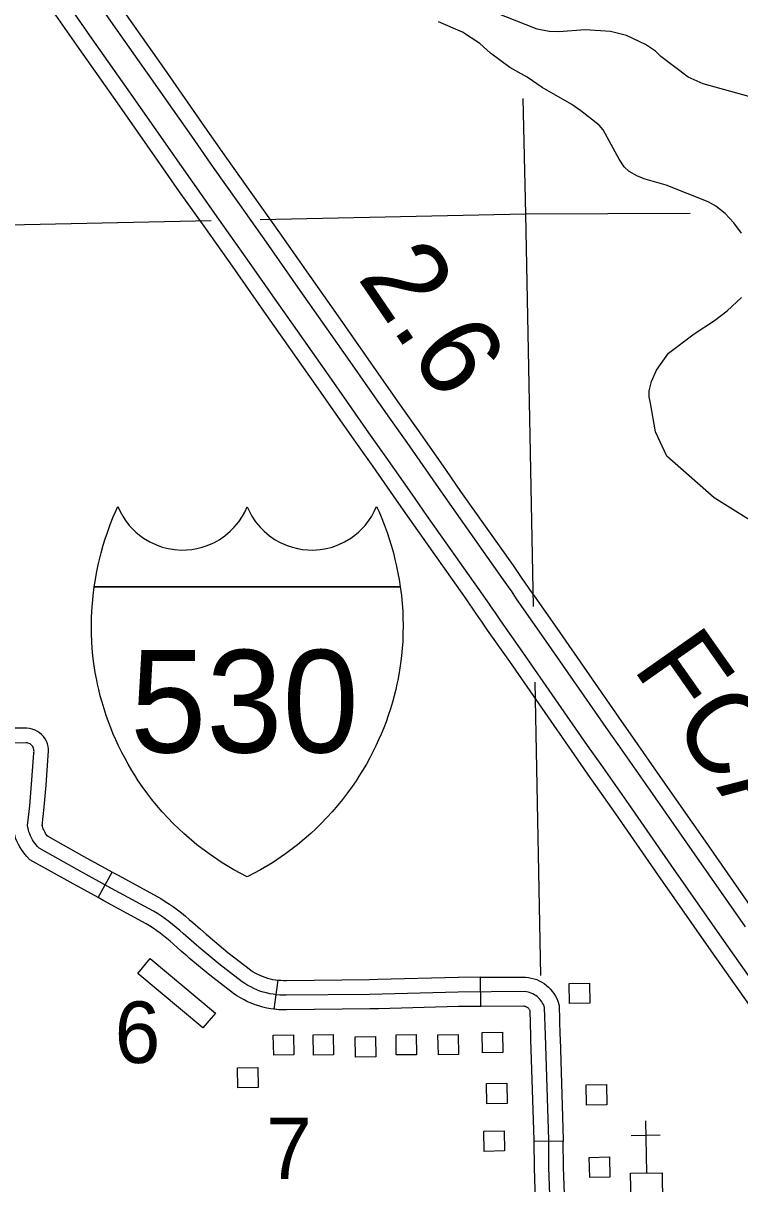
# Model space of a CAD drawing. Extents: x -19 to 366, y -4 to 359.
# Drawn here: x 157.737 to 158.436, y 175.04 to 176.172 of the extents above; entities that cross this region are included whole.
import ezdxf

# ---------------------------------------------------------------- set-up
doc = ezdxf.new("R2010")
doc.units = 0
for name, color, linetype in [('Level 19', 7, 'Continuous'), ('Level 23', 7, 'Continuous'), ('Level 26', 7, 'Continuous'), ('Level 31', 7, 'Continuous'), ('Level 35', 7, 'Continuous'), ('Level 47', 7, 'Continuous'), ('Level 48', 7, 'Continuous'), ('Level 5', 7, 'Continuous'), ('Level 56', 7, 'Continuous'), ('Level 57', 7, 'Continuous'), ('Level 60', 7, 'Continuous')]:
    doc.layers.add(name, color=color, linetype=linetype)

msp = doc.modelspace()

# ---------------------------------------------------------------- linework, layer by layer
at = {"layer": 'Level 19'}
for points in [[(157.777, 176.2397), (157.8247, 176.171), (157.8621, 176.1181), (157.9013, 176.0619), (157.9227, 176.0315), (157.9483, 175.9954), (157.9743, 175.9586), (158.0049, 175.9148), (158.0313, 175.8774), (158.0559, 175.8422), (158.0733, 175.8175), (158.0946, 175.787), (158.1116, 175.7632), (158.1369, 175.7268), (158.1512, 175.7062), (158.2024, 175.6339), (158.212, 175.6201), (158.2132, 175.6185), (158.2184, 175.6107), (158.2235, 175.6033), (158.245, 175.5728), (158.3081, 175.4819), (158.3213, 175.4632), (158.3486, 175.4241), (158.3897, 175.3651), (158.4416, 175.2906)], [(158.4685, 175.21), (158.4215, 175.2764), (158.3695, 175.351), (158.3284, 175.41), (158.3012, 175.4491), (158.2879, 175.4677), (158.2248, 175.5587), (158.2033, 175.5892), (158.198, 175.5969), (158.1933, 175.604), (158.1922, 175.6054), (158.1822, 175.6198), (158.1311, 175.6921), (158.1167, 175.7128), (158.0915, 175.749), (158.0745, 175.7728), (158.0531, 175.8034), (158.0358, 175.8281), (158.0111, 175.8633), (157.9848, 175.9007), (157.9541, 175.9444), (157.9282, 175.9812), (157.9026, 176.0172), (157.8811, 176.0478), (157.842, 176.1039), (157.8046, 176.1569), (157.7569, 176.2256)], [(157.7437, 176.2163), (157.7914, 176.1477), (157.8288, 176.0947), (157.8679, 176.0386), (157.8894, 176.0079), (157.9151, 175.9719), (157.941, 175.9352), (157.9716, 175.8914), (157.9979, 175.854), (158.0226, 175.8188), (158.0399, 175.7941), (158.0613, 175.7635), (158.0783, 175.7397), (158.1035, 175.7036), (158.1179, 175.6829), (158.169, 175.6106), (158.1793, 175.5958), (158.1803, 175.5945), (158.1847, 175.5879), (158.1901, 175.58), (158.2116, 175.5495), (158.2747, 175.4585), (158.288, 175.4398), (158.3152, 175.4008), (158.3563, 175.3418), (158.4083, 175.2672), (158.4553, 175.2007)], [(158.4548, 175.2999), (158.4029, 175.3743), (158.3618, 175.4333), (158.3345, 175.4725), (158.3212, 175.4911), (158.2582, 175.582), (158.2367, 175.6125), (158.2317, 175.6197), (158.2262, 175.628), (158.2249, 175.6297), (158.2156, 175.6432), (158.1644, 175.7155), (158.1501, 175.736), (158.1247, 175.7725), (158.1077, 175.7963), (158.0865, 175.8267), (158.0691, 175.8514), (158.0444, 175.8867), (158.0181, 175.9241), (157.9875, 175.9678), (157.9614, 176.0047), (157.9358, 176.0407), (157.9145, 176.0711), (157.8753, 176.1273), (157.8379, 176.1803)]]:
    msp.add_lwpolyline(points, dxfattribs=at)
at = {"layer": 'Level 23'}
for points in [[(157.8065, 175.6223), (157.8076, 175.6294), (157.8087, 175.6357), (157.8104, 175.6439), (157.8116, 175.6492), (157.8132, 175.6555), (157.8153, 175.6629), (157.8172, 175.6691), (157.8193, 175.6754), (157.8222, 175.6833), (157.8251, 175.6906), (157.8275, 175.6963), (157.8296, 175.7008), (157.8317, 175.696), (157.8343, 175.6914), (157.8371, 175.6871), (157.8407, 175.6824), (157.8436, 175.6792), (157.8471, 175.6758), (157.8507, 175.6728), (157.8546, 175.6699), (157.8608, 175.6662), (157.8672, 175.6633), (157.8729, 175.6612), (157.8786, 175.6598), (157.8847, 175.6588), (157.8918, 175.6583), (157.8965, 175.6584), (157.9018, 175.6589), (157.9066, 175.6597), (157.9117, 175.661), (157.9168, 175.6627), (157.9237, 175.6657), (157.9285, 175.6684), (157.934, 175.6722), (157.9393, 175.6766), (157.9432, 175.6805), (157.9476, 175.6859), (157.9513, 175.6914), (157.9534, 175.6952), (157.9558, 175.7003)], [(157.9558, 175.7003), (157.9582, 175.6952), (157.9603, 175.6914), (157.9639, 175.6859), (157.9684, 175.6805), (157.9722, 175.6766), (157.9776, 175.6722), (157.9831, 175.6684), (157.9879, 175.6657), (157.9948, 175.6627), (157.9999, 175.661), (158.005, 175.6597), (158.0098, 175.6589), (158.0151, 175.6584), (158.0198, 175.6583), (158.0269, 175.6588), (158.033, 175.6598), (158.0387, 175.6612), (158.0444, 175.6633), (158.0508, 175.6662), (158.057, 175.6699), (158.0609, 175.6728), (158.0645, 175.6758), (158.068, 175.6792), (158.0709, 175.6824), (158.0745, 175.6871), (158.0773, 175.6914), (158.0798, 175.696), (158.082, 175.7008), (158.0841, 175.6963), (158.0865, 175.6906), (158.0894, 175.6833), (158.0923, 175.6754), (158.0944, 175.6691), (158.0963, 175.6629), (158.0984, 175.6555), (158.1, 175.6492), (158.1012, 175.6439), (158.1029, 175.6357), (158.104, 175.6294), (158.1051, 175.6223)], [(157.9558, 175.3394), (157.9427, 175.3463), (157.9312, 175.3533), (157.9185, 175.3618), (157.9067, 175.3708), (157.8938, 175.3818), (157.889, 175.3863), (157.8835, 175.3916), (157.8784, 175.3969), (157.8728, 175.403), (157.8674, 175.4093), (157.8628, 175.415), (157.8579, 175.4214), (157.8534, 175.4276), (157.8495, 175.4333), (157.8461, 175.4386), (157.8432, 175.4432), (157.8395, 175.4495), (157.8366, 175.4548), (157.8334, 175.4609), (157.8303, 175.4672), (157.8276, 175.473), (157.8251, 175.4786), (157.8226, 175.485), (157.8203, 175.4908), (157.8182, 175.4969), (157.8161, 175.5033), (157.8141, 175.5099), (157.8124, 175.5161), (157.8109, 175.5221), (157.8097, 175.5274), (157.8089, 175.5313), (157.8075, 175.5389), (157.8061, 175.5477), (157.8052, 175.555), (157.8045, 175.5627), (157.8041, 175.5689), (157.8038, 175.5769), (157.8037, 175.5842), (157.8039, 175.5924), (157.8041, 175.5979), (157.8044, 175.6028), (157.8047, 175.6059), (157.8054, 175.614), (157.8065, 175.6223)], [(158.1051, 175.6223), (157.8065, 175.6223)], [(157.8065, 175.6223), (158.1051, 175.6223)], [(158.1051, 175.6223), (158.1062, 175.614), (158.1069, 175.6059), (158.1072, 175.6028), (158.1075, 175.5979), (158.1077, 175.5924), (158.1079, 175.5842), (158.1078, 175.5769), (158.1075, 175.5689), (158.1071, 175.5627), (158.1064, 175.555), (158.1055, 175.5477), (158.1041, 175.5389), (158.1027, 175.5313), (158.1019, 175.5274), (158.1007, 175.5221), (158.0992, 175.5161), (158.0975, 175.5099), (158.0955, 175.5033), (158.0934, 175.4969), (158.0913, 175.4908), (158.089, 175.485), (158.0865, 175.4786), (158.084, 175.473), (158.0813, 175.4672), (158.0782, 175.4609), (158.075, 175.4548), (158.0721, 175.4495), (158.0684, 175.4432), (158.0655, 175.4386), (158.0621, 175.4333), (158.0582, 175.4276), (158.0537, 175.4214), (158.0488, 175.415), (158.0442, 175.4093), (158.0388, 175.403), (158.0332, 175.3969), (158.0281, 175.3916), (158.0226, 175.3863), (158.0178, 175.3818), (158.0049, 175.3708), (157.9931, 175.3618), (157.9804, 175.3533), (157.9689, 175.3463), (157.9558, 175.3394)]]:
    msp.add_lwpolyline(points, dxfattribs=at)
at = {"layer": 'Level 31'}
for p, q in [((157.8102, 175.3193), (157.8239, 175.3442)), ((157.9101, 175.2885), (157.9101, 175.2885)), ((158.1836, 175.213), (158.1835, 175.2415)), ((157.9856, 175.2386), (157.9816, 175.2104)), ((158.2642, 175.0815), (158.2358, 175.0812)), ((158.2358, 175.0812), (158.2358, 175.0812))]:
    msp.add_line(p, q, dxfattribs=at)
for points in [[(157.7557, 175.3892), (157.7576, 175.4075), (157.7595, 175.4289), (157.7615, 175.458), (157.7617, 175.4586), (157.762, 175.4613), (157.7619, 175.4642), (157.7615, 175.4667), (157.7609, 175.4692), (157.7598, 175.4718), (157.7585, 175.4741), (157.757, 175.4763), (157.7552, 175.4782), (157.7532, 175.48), (157.7512, 175.4814), (157.7487, 175.4827), (157.746, 175.4837), (157.7434, 175.4843), (157.7407, 175.4846), (157.7241, 175.4844)], [(157.7439, 175.4692), (157.7429, 175.4697), (157.7419, 175.47), (157.741, 175.4702), (157.74, 175.4703), (157.6647, 175.4695), (157.6124, 175.4694)], [(157.9064, 175.2728), (157.8933, 175.2843), (157.89, 175.2873), (157.8865, 175.2902), (157.883, 175.2931), (157.8794, 175.2958), (157.8757, 175.2985), (157.872, 175.3011), (157.8682, 175.3036), (157.8644, 175.3059), (157.8228, 175.3285), (157.7899, 175.3466), (157.7526, 175.3675), (157.7511, 175.369), (157.7497, 175.3706), (157.7485, 175.3722), (157.7472, 175.3739), (157.7461, 175.3757), (157.7452, 175.3776), (157.7443, 175.3795), (157.7435, 175.3814), (157.7428, 175.3834), (157.7422, 175.3855), (157.7418, 175.3875), (157.7414, 175.3896), (157.7435, 175.4089), (157.7454, 175.43), (157.7474, 175.46), (157.7476, 175.4609), (157.7478, 175.4619), (157.7477, 175.4629), (157.7476, 175.4638), (157.7473, 175.4648), (157.747, 175.4657), (157.7465, 175.4665), (157.7459, 175.4673), (157.7453, 175.4681), (157.7445, 175.4687), (157.7439, 175.4692)], [(157.8102, 175.3193), (157.7831, 175.3342), (157.7438, 175.3561), (157.7406, 175.3594), (157.7387, 175.3616), (157.737, 175.3638), (157.7354, 175.3662), (157.7338, 175.3687), (157.7325, 175.3712), (157.7313, 175.3737), (157.7301, 175.3765), (157.7292, 175.3793), (157.7284, 175.382), (157.7278, 175.3848), (157.7271, 175.3892), (157.7274, 175.3921)], [(157.8239, 175.3442), (157.7968, 175.3591), (157.7614, 175.3788), (157.7607, 175.3796), (157.7599, 175.3806), (157.7591, 175.3817), (157.7585, 175.3828), (157.7579, 175.384), (157.7573, 175.3852), (157.7568, 175.3864), (157.7564, 175.3876), (157.756, 175.3889), (157.7558, 175.39), (157.7557, 175.3892)], [(157.8239, 175.3442), (157.8297, 175.341), (157.8715, 175.3182), (157.8758, 175.3155), (157.8799, 175.3129), (157.8839, 175.3101), (157.8879, 175.3072), (157.8917, 175.3043), (157.8956, 175.3012), (157.8993, 175.298), (157.9027, 175.295), (157.9101, 175.2885)], [(157.8914, 175.2671), (157.8839, 175.2737), (157.8807, 175.2766), (157.8775, 175.2793), (157.8742, 175.2819), (157.8709, 175.2844), (157.8675, 175.2869), (157.8641, 175.2893), (157.8605, 175.2916), (157.8572, 175.2937), (157.816, 175.3161), (157.8102, 175.3193)], [(157.9101, 175.2885), (157.9158, 175.2835), (157.9177, 175.2818), (157.937, 175.2657), (157.959, 175.2487), (157.9611, 175.2473), (157.9633, 175.246), (157.9657, 175.2447), (157.9681, 175.2435), (157.9705, 175.2425), (157.973, 175.2415), (157.9755, 175.2407), (157.9781, 175.24), (157.9806, 175.2394), (157.9833, 175.2389), (157.9856, 175.2386)], [(157.9816, 175.2104), (157.9787, 175.2108), (157.9748, 175.2115), (157.971, 175.2124), (157.9672, 175.2135), (157.9635, 175.2147), (157.9598, 175.2161), (157.9562, 175.2177), (157.9527, 175.2194), (157.9492, 175.2213), (157.9458, 175.2233), (157.9424, 175.2256), (157.9192, 175.2436), (157.8992, 175.2603), (157.8971, 175.2622), (157.8914, 175.2671)], [(158.2521, 175.0029), (158.2502, 175.056), (158.25, 175.0828), (158.2468, 175.1849), (158.246, 175.2116), (158.2455, 175.2132), (158.2448, 175.2148), (158.2441, 175.2162), (158.2432, 175.2177), (158.2422, 175.219), (158.2412, 175.2203), (158.24, 175.2215), (158.2387, 175.2226), (158.2374, 175.2236), (158.236, 175.2245), (158.2345, 175.2253), (158.233, 175.226), (158.2314, 175.2265), (158.2298, 175.227), (158.2282, 175.2273), (158.2265, 175.2275), (158.1617, 175.2271), (158.0752, 175.2248), (157.9941, 175.2239), (157.9908, 175.2239), (157.9875, 175.2241), (157.9842, 175.2244), (157.981, 175.2249), (157.9777, 175.2255), (157.9745, 175.2262), (157.9714, 175.2271), (157.9682, 175.2281), (157.9652, 175.2293), (157.9621, 175.2306), (157.9592, 175.2321), (157.9563, 175.2336), (157.9534, 175.2353), (157.9507, 175.2372), (157.9281, 175.2546), (157.9085, 175.271), (157.9064, 175.2728)], [(158.1835, 175.2415), (158.1615, 175.2413), (158.0832, 175.2392)], [(158.1835, 175.2415), (158.2273, 175.2417), (158.2304, 175.2413), (158.233, 175.2408), (158.2357, 175.2401), (158.2383, 175.2392), (158.2408, 175.2381), (158.2432, 175.2367), (158.2455, 175.2353), (158.2477, 175.2336), (158.2497, 175.2318), (158.2517, 175.2298), (158.2535, 175.2277), (158.255, 175.2256), (158.2565, 175.2232), (158.2578, 175.2207), (158.2588, 175.2182), (158.2601, 175.2141), (158.261, 175.1853), (158.2611, 175.1818)], [(158.0832, 175.2392), (158.075, 175.239), (157.9941, 175.2381), (157.9912, 175.2381), (157.9885, 175.2383), (157.9859, 175.2385), (157.9856, 175.2386)], [(158.084, 175.2108), (158.0755, 175.2106), (157.9942, 175.2097), (157.9904, 175.2097), (157.9865, 175.2099), (157.9826, 175.2103), (157.9816, 175.2104)], [(158.1836, 175.213), (158.1619, 175.2129), (158.084, 175.2108)], [(158.2327, 175.1809), (158.2326, 175.1845), (158.2319, 175.2089), (158.2317, 175.2093), (158.2314, 175.2098), (158.231, 175.2103), (158.2306, 175.2108), (158.2303, 175.2111), (158.2298, 175.2116), (158.2293, 175.2119), (158.2288, 175.2123), (158.2283, 175.2125), (158.2277, 175.2128), (158.2272, 175.213), (158.2266, 175.2131), (158.226, 175.2132), (158.2257, 175.2133), (158.1836, 175.213)], [(158.2358, 175.0812), (158.2358, 175.0825), (158.2327, 175.1809)], [(158.2611, 175.1818), (158.2642, 175.0831), (158.2642, 175.0815)], [(158.2707, 174.996), (158.2701, 174.9965), (158.2695, 174.997), (158.2689, 174.9975), (158.2684, 174.9981), (158.268, 174.9987), (158.2676, 174.9994), (158.2673, 175.0001), (158.2669, 175.0009), (158.2667, 175.0016), (158.2665, 175.0023), (158.2663, 175.0031), (158.2663, 175.0039), (158.2644, 175.0563), (158.2642, 175.0815)], [(158.2535, 174.9734), (158.252, 174.9745), (158.2498, 174.9764), (158.2479, 174.9785), (158.246, 174.9807), (158.2443, 174.9831), (158.2428, 174.9855), (158.2415, 174.9881), (158.2404, 174.9907), (158.2395, 174.9934), (158.2387, 174.9962), (158.2382, 174.999), (158.2379, 175.0019), (158.236, 175.0557), (158.2358, 175.0812)]]:
    msp.add_lwpolyline(points, dxfattribs=at)
at = {"layer": 'Level 35'}
msp.add_lwpolyline([(158.484, 176.0899), (158.4006, 176.1131), (158.3862, 176.1197), (158.3595, 176.1397), (158.3543, 176.1449), (158.3444, 176.1516), (158.326, 176.1603), (158.3104, 176.164), (158.2856, 176.1657), (158.26, 176.1637), (158.2503, 176.1641), (158.2386, 176.1665), (158.1882, 176.1863)], dxfattribs=at)
at = {"layer": 'Level 47'}
for points in [[(158.4381, 175.9675), (158.4307, 175.9774), (158.4222, 175.9866), (158.4132, 175.9936), (158.4056, 175.998), (158.3645, 176.0144), (158.344, 176.0201), (158.3365, 176.023), (158.3285, 176.0276), (158.3237, 176.0322), (158.3186, 176.0397), (158.303, 176.0681), (158.2993, 176.0729), (158.2814, 176.0869), (158.2726, 176.093), (158.2435, 176.1095), (158.2289, 176.1197), (158.2119, 176.1291), (158.1933, 176.1429), (158.1827, 176.1526), (158.1658, 176.1635), (158.1423, 176.1735)], [(158.4728, 175.671), (158.4115, 175.7091), (158.3653, 175.75), (158.3541, 175.7736), (158.3494, 175.8016), (158.348, 175.8076), (158.3481, 175.8135), (158.3504, 175.8227), (158.3553, 175.8339), (158.3668, 175.8505), (158.3918, 175.8691), (158.4117, 175.8822), (158.4242, 175.8917), (158.4382, 175.9045)]]:
    msp.add_lwpolyline(points, dxfattribs=at)
at = {"layer": 'Level 5'}
for points in [[(158.2248, 176.0989), (158.2275, 175.9858)], [(157.9205, 175.9793), (157.1612, 175.9631)], [(158.2275, 175.9858), (157.9685, 175.9803)], [(158.3882, 175.9866), (158.2275, 175.9858)], [(158.2275, 175.9858), (158.2349, 175.6033)], [(158.2363, 175.5294), (158.2419, 175.2434)]]:
    msp.add_lwpolyline(points, dxfattribs=at)
at = {"layer": 'Level 56'}
for points in [[(157.849, 175.2453), (157.8612, 175.2598), (157.9247, 175.2066), (157.9125, 175.1921)], [(158.2703, 175.2159), (158.27, 175.2356), (158.2897, 175.2359), (158.2901, 175.2162)], [(157.9816, 175.1654), (157.9812, 175.1851), (158.001, 175.1854), (158.0013, 175.1657)], [(158.0204, 175.1656), (158.02, 175.1853), (158.0398, 175.1857), (158.0401, 175.166)], [(158.0615, 175.1636), (158.0611, 175.1833), (158.0809, 175.1837), (158.0813, 175.164)], [(158.1013, 175.1657), (158.101, 175.1854), (158.1207, 175.1857), (158.1211, 175.166)], [(158.1423, 175.1657), (158.1419, 175.1854), (158.1617, 175.1858), (158.162, 175.1661)], [(158.1855, 175.1678), (158.1851, 175.1875), (158.2049, 175.1879), (158.2052, 175.1682)], [(157.9466, 175.1336), (157.9462, 175.1533), (157.966, 175.1536), (157.9664, 175.1339)], [(158.1896, 175.1182), (158.1892, 175.1379), (158.209, 175.1382), (158.2093, 175.1185)], [(158.2869, 175.1168), (158.2865, 175.1365), (158.3063, 175.1368), (158.3066, 175.1171)], [(158.187, 175.0717), (158.1866, 175.0914), (158.2064, 175.0918), (158.2068, 175.0721)], [(158.29, 175.0461), (158.2896, 175.0658), (158.3094, 175.0662), (158.3098, 175.0465)]]:
    msp.add_lwpolyline(points, close=True, dxfattribs=at)
at = {"layer": 'Level 57'}
for p, q in [((158.3444, 175.1016), (158.3453, 175.0506)), ((158.3304, 175.0871), (158.3588, 175.0877))]:
    msp.add_line(p, q, dxfattribs=at)
msp.add_lwpolyline([(158.3304, 175.0208), (158.3299, 175.0503), (158.3606, 175.0509), (158.3611, 175.0213)], close=True, dxfattribs=at)
at = {"layer": 'Level 60'}
for points in [[(161.4532, 2.0533), (161.2336, 10.6702), (161.0133, 19.2873), (160.7922, 27.9044), (160.5704, 36.5217), (160.3478, 45.1392), (160.1245, 53.7568), (159.9003, 62.3745), (159.6754, 70.9923), (159.4498, 79.6103), (159.2234, 88.2284), (158.9962, 96.8466), (158.7683, 105.465), (158.5396, 114.0835), (158.3102, 122.7022), (158.08, 131.321), (157.849, 139.9399), (157.6173, 148.559), (157.3849, 157.1782), (157.1517, 165.7975), (156.9177, 174.417), (156.683, 183.0366), (156.511, 189.3363)], [(0, 172.2839), (7.1335, 172.2883), (14.267, 172.3015), (21.4005, 172.3236), (28.5339, 172.3544), (35.6673, 172.3941), (42.8006, 172.4426), (49.9339, 172.4999), (57.0671, 172.566), (64.2002, 172.6409), (71.3332, 172.7246), (78.4661, 172.8172), (85.5989, 172.9186), (92.7315, 173.0287), (99.8641, 173.1477), (106.9964, 173.2755), (114.1286, 173.4122), (121.2606, 173.5576), (128.3925, 173.7119), (135.5241, 173.8749), (142.6555, 174.0468), (149.7867, 174.2275), (156.9177, 174.417), (164.0485, 174.6153), (171.179, 174.8224), (178.3092, 175.0383), (185.4392, 175.2631), (192.5688, 175.4966), (199.6982, 175.739), (206.8273, 175.9902), (213.9561, 176.2502), (221.0845, 176.5189), (228.2126, 176.7965), (235.3404, 177.083), (242.4677, 177.3782), (249.5948, 177.6822), (256.7214, 177.995), (263.8476, 178.3167), (270.9735, 178.6471), (278.0989, 178.9863), (285.2239, 179.3344), (292.3485, 179.6912), (299.4726, 180.0569), (306.5963, 180.4314), (313.7195, 180.8146), (320.8422, 181.2067), (327.9644, 181.6076), (335.0862, 182.0172), (342.2074, 182.4357)]]:
    msp.add_spline(points, degree=3, dxfattribs=at)

# ---------------------------------------------------------------- texts
at = {"layer": 'Level 23'}
msp.add_text('530', height=0.1, dxfattribs=at).set_placement((157.8415, 175.4608))
at = {"layer": 'Level 26'}
msp.add_text('FCA', height=0.08, rotation=305.0896, dxfattribs=at).set_placement((158.3311, 175.5434))
at = {"layer": 'Level 48'}
msp.add_text('2.6', height=0.08, rotation=304.3054, dxfattribs=at).set_placement((158.0626, 175.9242))
at = {"layer": 'Level 56'}
for s, p in [('6', (157.8264, 175.1579)), ('7', (157.9743, 175.0446))]:
    msp.add_text(s, height=0.06, dxfattribs=at).set_placement(p)

doc.saveas('drawing.dxf')
